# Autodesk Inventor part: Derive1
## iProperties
Created: 2008-04
Part Number: Derive1
Document SubType Name: Modeling
Designer: JWe
Density: 1 g/cm^3
Author: JWe
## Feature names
1. Sweep1
2. Fillet1
3. Fillet2
4. Shell1
5. Split2
